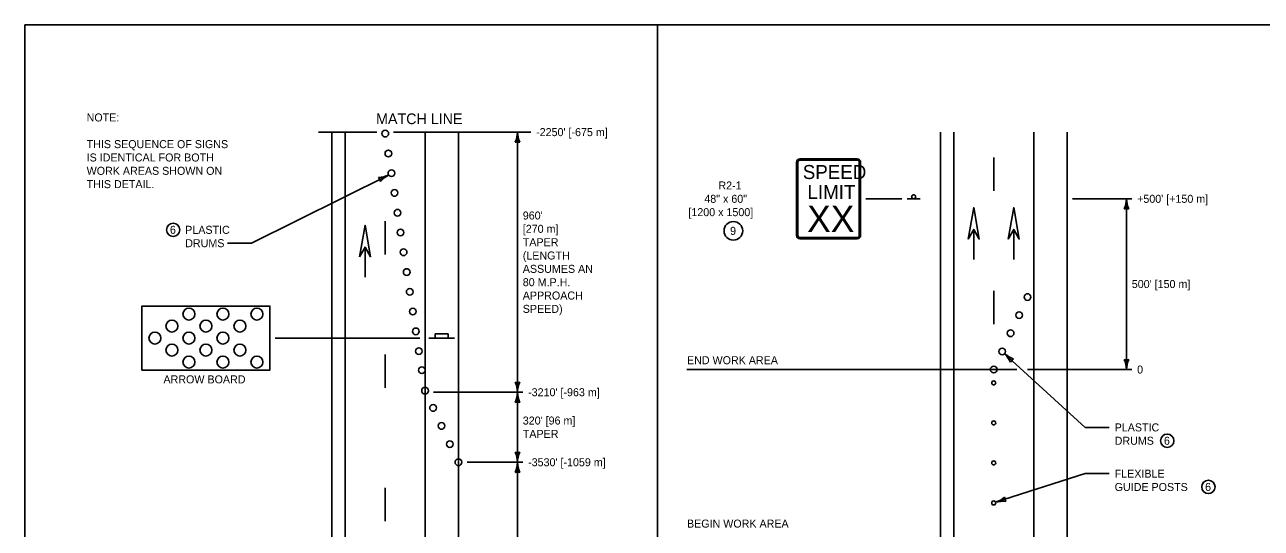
# Model space of a CAD drawing. Extents: x 49991.4 to 50021, y 49987.6 to 50011.4.
# Drawn here: x 49999.38 to 50008.66, y 49995.22 to 49999 of the extents above; entities that cross this region are included whole.
import ezdxf

# ---------------------------------------------------------------- set-up
doc = ezdxf.new("R2010")
doc.units = 0
for name, color, linetype in [('Level 1', 7, 'Continuous'), ('Level 2', 7, 'Continuous'), ('Level 3', 7, 'Continuous'), ('Level 6', 7, 'Continuous')]:
    doc.layers.add(name, color=color, linetype=linetype)

msp = doc.modelspace()

# ---------------------------------------------------------------- linework, layer by layer
at = {"layer": 'Level 1'}
for p, q in [((50001.6854, 49991.1511), (50001.6854, 49998.194)), ((50001.7854, 49991.1511), (50001.7854, 49998.194)), ((50002.3854, 49991.1511), (50002.3854, 49998.194)), ((50002.6354, 49991.1511), (50002.6354, 49998.194)), ((50006.25, 49989.429), (50006.25, 49998.194)), ((50006.35, 49989.429), (50006.35, 49998.194)), ((50006.95, 49989.4296), (50006.95, 49998.194)), ((50007.2, 49989.4294), (50007.2, 49998.194)), ((50005.172, 49997.419), (50005.172, 49997.969)), ((50005.182, 49997.419), (50005.182, 49997.969)), ((50005.197, 49997.994), (50005.627, 49997.994)), ((50005.197, 49997.984), (50005.627, 49997.984)), ((50005.642, 49997.969), (50005.642, 49997.419)), ((50005.652, 49997.969), (50005.652, 49997.419)), ((50006.65, 49997.7546), (50006.65, 49998.0046)), ((50006.002, 49997.694), (50006.098, 49997.694)), ((50002.0854, 49997.277), (50002.0854, 49997.527)), ((50006.4997, 49997.2386), (50006.4997, 49997.4645)), ((50006.5, 49997.2386), (50006.5, 49997.4645)), ((50006.7997, 49997.2386), (50006.7997, 49997.4645)), ((50006.8, 49997.2386), (50006.8, 49997.4645)), ((50005.627, 49997.404), (50005.197, 49997.404)), ((50005.627, 49997.394), (50005.197, 49997.394)), ((50001.9354, 49997.106), (50001.9354, 49997.3319)), ((50001.9357, 49997.106), (50001.9357, 49997.3319)), ((50006.65, 49996.7546), (50006.65, 49997.0046)), ((50002.6064, 49996.6503), (50002.4144, 49996.6503)), ((50002.0854, 49996.277), (50002.0854, 49996.527)), ((50002.0854, 49995.277), (50002.0854, 49995.527))]:
    msp.add_line(p, q, dxfattribs=at)
for points in [[(49999.3835, 49998.9992), (50016.7501, 49998.9992), (50016.7501, 49987.7988), (49999.3835, 49987.7988)], [(50006.458, 49997.3922), (50006.4997, 49997.6287), (50006.5416, 49997.3922), (50006.4997, 49997.4644)], [(50006.758, 49997.3922), (50006.7997, 49997.6287), (50006.8416, 49997.3922), (50006.7997, 49997.4644)], [(50001.8937, 49997.2596), (50001.9354, 49997.4961), (50001.9773, 49997.2596), (50001.9354, 49997.3318)], [(50000.2626, 49996.4103), (50001.2226, 49996.4103), (50001.2226, 49996.8903), (50000.2626, 49996.8903)], [(50000.2626, 49996.4103), (50001.2226, 49996.4103), (50001.2226, 49996.8903), (50000.2626, 49996.8903)], [(50002.4624, 49996.6807), (50002.5584, 49996.6807), (50002.5584, 49996.6503), (50002.4624, 49996.6503)]]:
    msp.add_lwpolyline(points, close=True, dxfattribs=at)
for centre, radius in [((50002.0872, 49998.1828), 0.025), ((50002.1102, 49998.0345), 0.025), ((50002.1331, 49997.8863), 0.025), ((50002.156, 49997.738), 0.025), ((50006.05, 49997.7092), 0.0152), ((50002.1789, 49997.5898), 0.025), ((50002.2018, 49997.4416), 0.025), ((50002.2248, 49997.2933), 0.025), ((50002.2477, 49997.1451), 0.025), ((50002.2706, 49996.9969), 0.025), ((50006.9037, 49996.9577), 0.025), ((50000.6151, 49996.8303), 0.045), ((50000.6151, 49996.8303), 0.045), ((50000.8701, 49996.8303), 0.045), ((50000.8701, 49996.8303), 0.045), ((50001.1251, 49996.8303), 0.045), ((50001.1251, 49996.8303), 0.045), ((50002.2935, 49996.8486), 0.025), ((50006.8403, 49996.8218), 0.025), ((50000.4876, 49996.7403), 0.045), ((50000.4876, 49996.7403), 0.045), ((50000.7426, 49996.7403), 0.045), ((50000.7426, 49996.7403), 0.045), ((50000.9976, 49996.7403), 0.045), ((50000.9976, 49996.7403), 0.045), ((50002.3165, 49996.7004), 0.025), ((50006.7769, 49996.6858), 0.025), ((50000.3601, 49996.6503), 0.045), ((50000.3601, 49996.6503), 0.045), ((50000.6151, 49996.6503), 0.045), ((50000.6151, 49996.6503), 0.045), ((50000.8701, 49996.6503), 0.045), ((50000.8701, 49996.6503), 0.045), ((50000.4876, 49996.5603), 0.045), ((50000.4876, 49996.5603), 0.045), ((50000.7426, 49996.5603), 0.045), ((50000.7426, 49996.5603), 0.045), ((50000.9976, 49996.5603), 0.045), ((50000.9976, 49996.5603), 0.045), ((50002.3394, 49996.5521), 0.025), ((50006.7135, 49996.5499), 0.025), ((50000.6151, 49996.4703), 0.045), ((50000.6151, 49996.4703), 0.045), ((50000.8701, 49996.4703), 0.045), ((50000.8701, 49996.4703), 0.045), ((50001.1251, 49996.4703), 0.045), ((50001.1251, 49996.4703), 0.045), ((50002.3619, 49996.4089), 0.025), ((50006.6501, 49996.414), 0.025), ((50002.3852, 49996.2556), 0.025), ((50006.65, 49996.314), 0.015), ((50002.4455, 49996.1262), 0.025), ((50002.5084, 49995.9912), 0.025), ((50006.65, 49996.014), 0.015), ((50002.5713, 49995.8544), 0.025), ((50002.6354, 49995.7188), 0.025), ((50006.65, 49995.714), 0.015), ((50006.65, 49995.414), 0.015)]:
    msp.add_circle(centre, radius, dxfattribs=at)
for centre, radius, start, end in [((50005.197, 49997.969), 0.025, 90, 180), ((50005.197, 49997.969), 0.015, 90, 180), ((50005.627, 49997.969), 0.025, 0, 90), ((50005.627, 49997.969), 0.015, 0, 90), ((50005.197, 49997.419), 0.025, 180, 270), ((50005.197, 49997.419), 0.015, 180, 270), ((50005.627, 49997.419), 0.025, 270, 0), ((50005.627, 49997.419), 0.015, 270, 0)]:
    msp.add_arc(centre, radius, start, end, dxfattribs=at)
at = {"layer": 'Level 2'}
for centre, radius in [((50000.4968, 49997.4615), 0.05), ((50004.6976, 49997.454), 0.07), ((50007.9511, 49995.8802), 0.05), ((50008.2598, 49995.5338), 0.05)]:
    msp.add_circle(centre, radius, dxfattribs=at)
at = {"layer": 'Level 3'}
for p, q in [((50004.1287, 49998.9992), (50004.1287, 49987.7988)), ((50003.0784, 49998.194), (50003.0784, 49996.244)), ((50002.1123, 49997.8724), (50001.0837, 49997.3615)), ((50005.962, 49997.694), (50005.692, 49997.694)), ((50007.6854, 49997.694), (50007.24, 49997.694)), ((50007.6454, 49996.414), (50007.6454, 49997.694)), ((50001.0837, 49997.3615), (50000.9037, 49997.3615)), ((50002.3454, 49996.6503), (50001.2626, 49996.6503)), ((50006.7319, 49996.533), (50007.337, 49995.9801)), ((50006.8222, 49996.414), (50004.3498, 49996.414)), ((50007.6854, 49996.414), (50006.9022, 49996.414)), ((50003.1184, 49996.244), (50002.4501, 49996.244)), ((50003.0784, 49996.2442), (50003.0784, 49995.719)), ((50007.337, 49995.9801), (50007.517, 49995.9801)), ((50003.1184, 49995.719), (50002.7004, 49995.719)), ((50003.0784, 49995.719), (50003.0784, 49994.459)), ((50006.6643, 49995.4186), (50007.337, 49995.6335)), ((50007.337, 49995.6335), (50007.517, 49995.6335))]:
    msp.add_line(p, q, dxfattribs=at)
for centre, radius, start, end in [((50002.8562, 49998.2032), 0.2223, 337.45601, 357.63952), ((50003.0784, 49998.0658), 0.0548, 72.13882, 107.86118), ((50003.3111, 49998.2055), 0.233, 182.82731, 202.07716), ((50002.0217, 49998.0754), 0.2223, 273.86716, 294.05067), ((50001.9975, 49997.8154), 0.0548, 8.54997, 44.27233), ((50002.2261, 49997.6691), 0.233, 119.23846, 138.48831), ((50007.4127, 49997.7055), 0.233, 337.92284, 357.17269), ((50007.8676, 49997.7032), 0.2223, 182.36048, 202.54399), ((50007.6454, 49997.5658), 0.0548, 72.13882, 107.86118), ((50006.8781, 49996.7005), 0.2223, 228.88386, 249.06736), ((50006.5635, 49996.3721), 0.233, 24.44621, 43.69606), ((50006.825, 49996.4448), 0.0548, 118.66219, 154.38456), ((50007.4233, 49996.4048), 0.2223, 2.36048, 22.54399), ((50007.6454, 49996.5422), 0.0548, 252.13882, 287.86118), ((50007.8782, 49996.4025), 0.233, 157.92284, 177.17269), ((50003.0784, 49996.3722), 0.0548, 252.13882, 287.86118), ((50002.8457, 49996.2325), 0.233, 2.82731, 22.07716), ((50003.3005, 49996.2348), 0.2223, 157.45601, 177.63952), ((50002.8562, 49996.2532), 0.2223, 337.45601, 357.63952), ((50003.0784, 49996.1158), 0.0548, 72.13882, 107.86118), ((50003.3111, 49996.2555), 0.233, 182.82731, 202.07716), ((50003.0784, 49995.8472), 0.0548, 252.13882, 287.86118), ((50002.8457, 49995.7075), 0.233, 2.82731, 22.07716), ((50003.3005, 49995.7098), 0.2223, 157.45601, 177.63952), ((50002.8562, 49995.7282), 0.2223, 337.45601, 357.63952), ((50003.3111, 49995.7305), 0.233, 182.82731, 202.07716), ((50003.0784, 49995.5908), 0.0548, 72.13882, 107.86118), ((50006.5826, 49995.6367), 0.233, 290.54921, 309.79906), ((50006.7232, 49995.2042), 0.2223, 85.17791, 105.36142), ((50006.7865, 49995.4576), 0.0548, 179.86072, 215.58308)]:
    msp.add_arc(centre, radius, start, end, dxfattribs=at)
at = {"layer": 'Level 6'}
for p, q in [((50002.0249, 49998.194), (50001.5854, 49998.194)), ((50002.1496, 49998.194), (50003.1784, 49998.194))]:
    msp.add_line(p, q, dxfattribs=at)

# ---------------------------------------------------------------- texts
at = {"layer": 'Level 1'}
for s, height, p in [('SPEED', 0.10512, (50005.2182, 49997.8424)), ('LIMIT', 0.10512, (50005.2536, 49997.6923)), ('XX', 0.19892, (50005.2505, 49997.445))]:
    msp.add_text(s, height=height, dxfattribs=at).set_placement(p)
at = {"layer": 'Level 2'}
for s, height, p in [('NOTE:', 0.06, (49999.8478, 49998.274)), ('MATCH LINE', 0.08, (50002.0184, 49998.254)), ("-2250' [-675 m]", 0.06, (50003.2184, 49998.164)), ('THIS SEQUENCE OF SIGNS', 0.06, (49999.8478, 49998.074)), ('IS IDENTICAL FOR BOTH', 0.06, (49999.8478, 49997.974)), ('WORK AREAS SHOWN ON', 0.06, (49999.8478, 49997.874)), ('THIS DETAIL.', 0.06, (49999.8478, 49997.774)), ('R2-1', 0.06, (50004.5854, 49997.764)), ('48" x 60"', 0.06, (50004.4799, 49997.664)), ("+500' [+150 m]", 0.06, (50007.7254, 49997.664)), ("960' ", 0.06, (50003.1184, 49997.539)), ('[1200 x 1500]', 0.06, (50004.3604, 49997.564)), ('6', 0.06, (50000.4723, 49997.4315)), ('PLASTIC', 0.06, (50000.5868, 49997.4315)), ('[270 m]', 0.06, (50003.1184, 49997.439)), ('9', 0.06, (50004.6731, 49997.424)), ('DRUMS', 0.06, (50000.5868, 49997.3315)), ('TAPER', 0.06, (50003.1184, 49997.339)), ('(LENGTH', 0.06, (50003.1184, 49997.239)), ('ASSUMES AN', 0.06, (50003.1184, 49997.139)), ('80 M.P.H.', 0.06, (50003.1184, 49997.039)), ("500' [150 m]", 0.06, (50007.6854, 49997.0251)), ('APPROACH', 0.06, (50003.1184, 49996.939)), ('SPEED)', 0.06, (50003.1184, 49996.839)), ('END WORK AREA', 0.06, (50004.3498, 49996.454)), ('0', 0.06, (50007.7254, 49996.384)), ('ARROW BOARD', 0.06, (50000.4239, 49996.3103)), ("-3210' [-963 m]", 0.06, (50003.1584, 49996.214)), ("320' [96 m]", 0.06, (50003.1184, 49996.0016)), ('PLASTIC', 0.06, (50007.557, 49995.9502)), ('TAPER', 0.06, (50003.1184, 49995.9016)), ('DRUMS', 0.06, (50007.557, 49995.8502)), ('6', 0.06, (50007.9266, 49995.8502)), ("-3530' [-1059 m]", 0.06, (50003.1584, 49995.689)), ('FLEXIBLE', 0.06, (50007.557, 49995.6035)), ('GUIDE POSTS', 0.06, (50007.557, 49995.5035)), ('6', 0.06, (50008.2353, 49995.5038)), ('BEGIN WORK AREA', 0.06, (50004.3498, 49995.229))]:
    msp.add_text(s, height=height, dxfattribs=at).set_placement(p)

doc.saveas('drawing.dxf')
